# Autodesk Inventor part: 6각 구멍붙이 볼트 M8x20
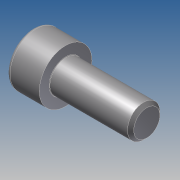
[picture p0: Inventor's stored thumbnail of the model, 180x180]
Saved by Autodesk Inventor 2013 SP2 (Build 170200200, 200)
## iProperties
Created: 2025-06
Part Number: 6각 구멍붙이 볼트 M8x20
Material: Generic
Document SubType Name: Modeling
Designer: i
Density: 1 g/cm^3
Author: i
변환 표준: STEP AP214IS
전처리기: Build: 200, Release: 2013 SP2 Update 6 - Date: Thu 07/17/2014
전송 단위: 밀리미터
불확실성: 0.01
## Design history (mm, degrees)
node "6각 구멍붙이 볼트 M8x201"
body "Solid1"
node "기준1"
